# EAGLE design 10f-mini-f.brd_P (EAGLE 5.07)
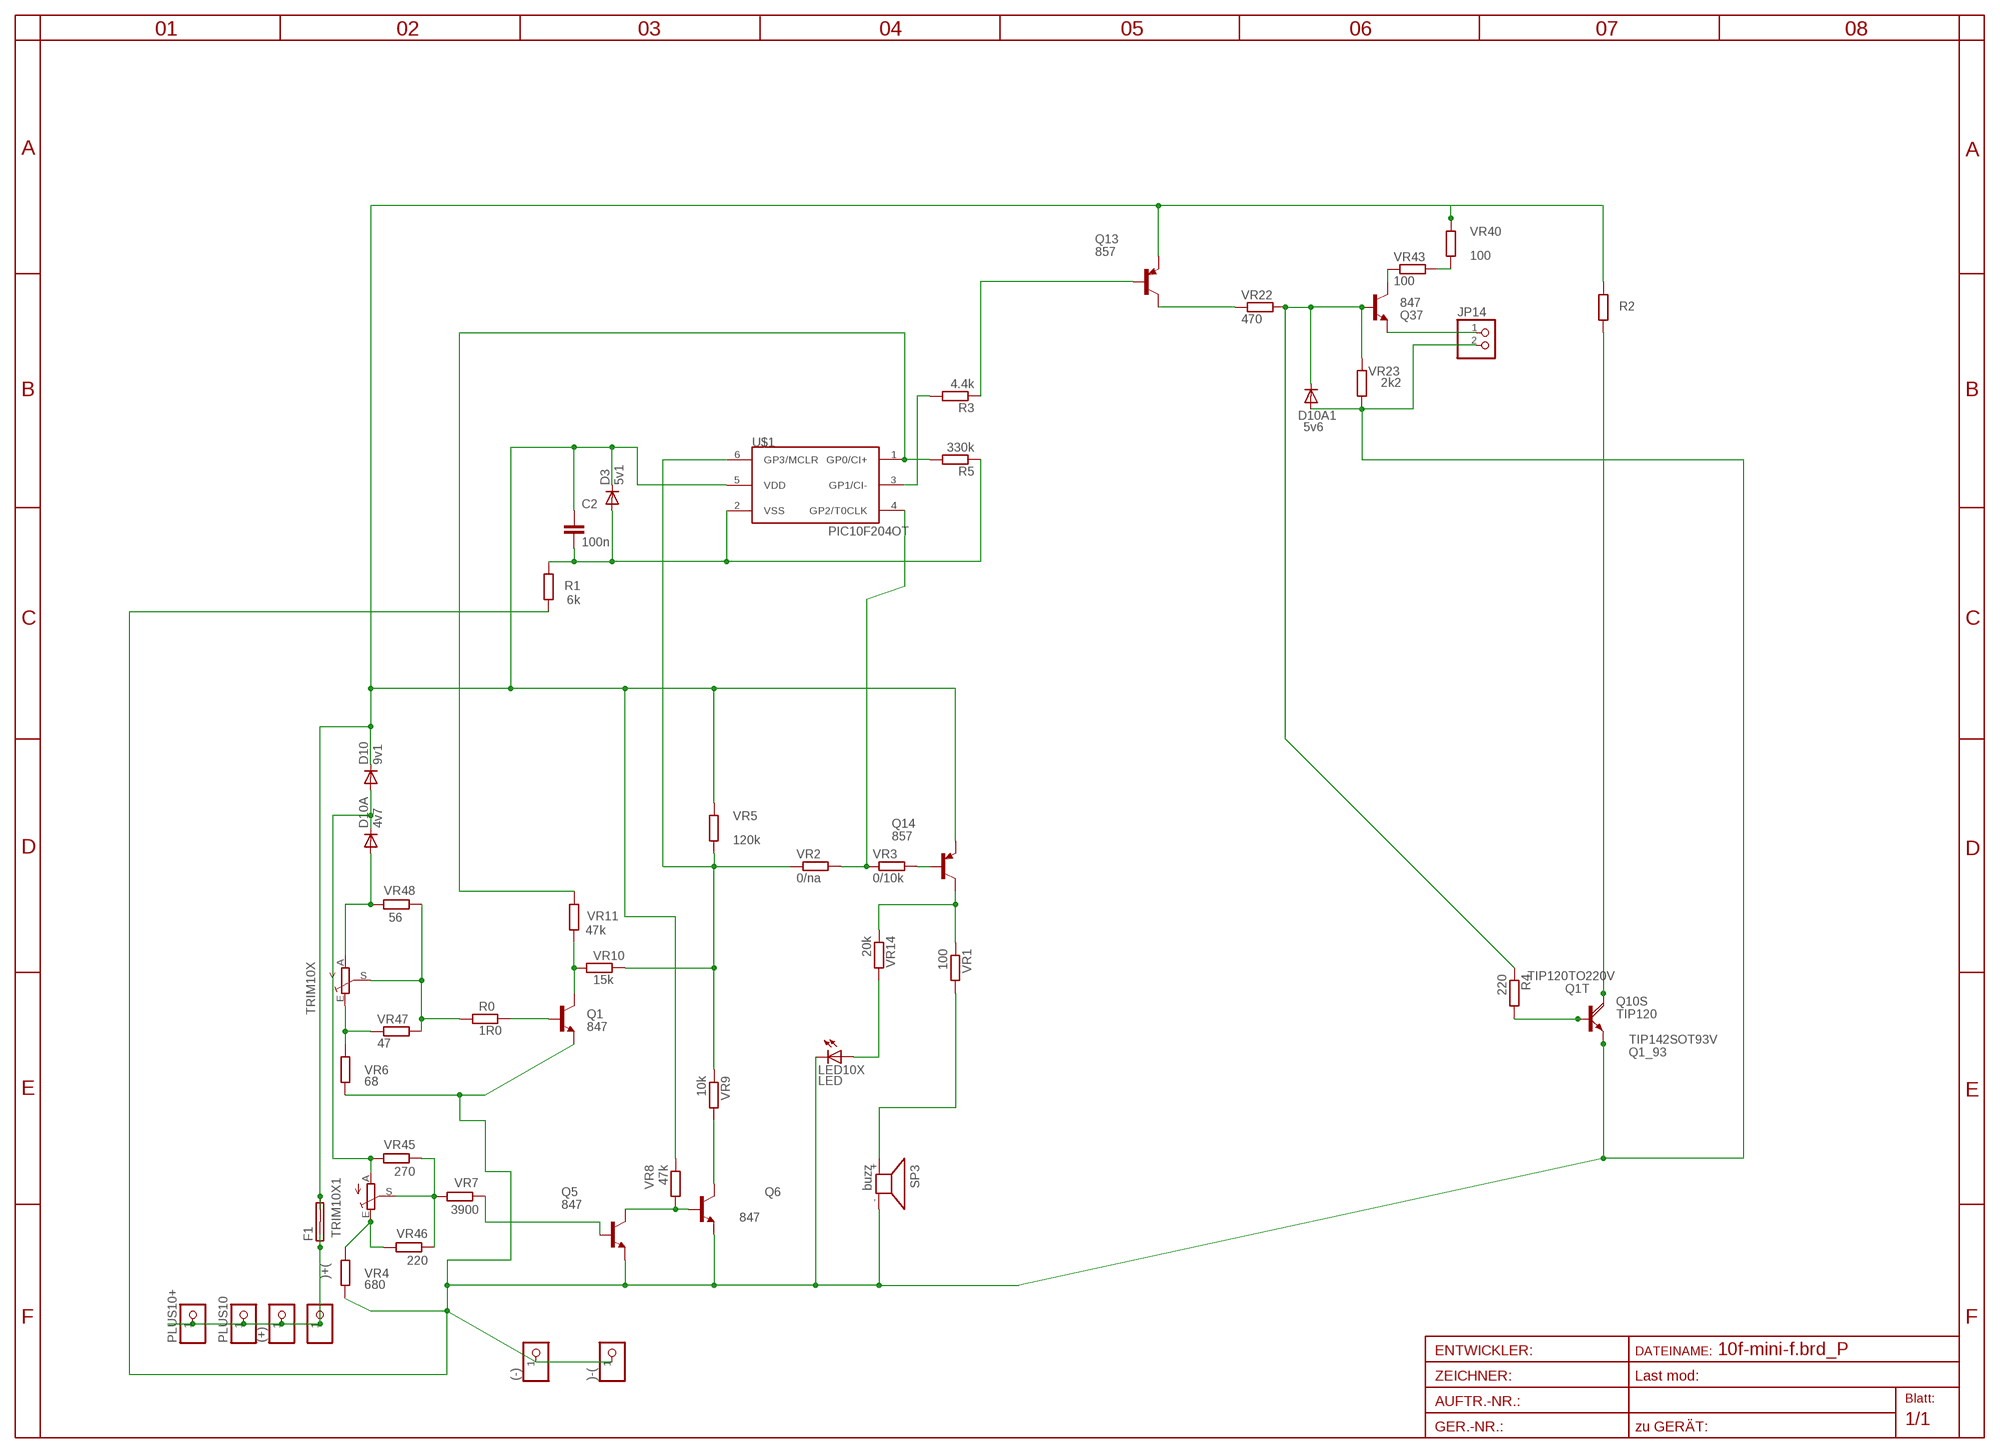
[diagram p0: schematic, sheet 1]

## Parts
(+)  PINHD-1X14.5MM  [1X4MM5]
(-)  PINHD-1X14.5MM  [1X4MM5]
)+(  PINHD-1X11X0.4  [1X01]
)-(  PINHD-1X11X0.4  [1X01]
C2  100n  C-EUC0805  [C0805]
D3  5v1  DIODE-MINIMELF  [MINIMELF]
D10  9v1  DIODE-MINIMELF  [MINIMELF]
D10A  4v7  DIODE-MINIMELF  [MINIMELF]
D10A1  5v6  DIODE-MINIMELF  [MINIMELF]
F1  SHK20L7MM5  [7MM5]
JP14  PINHD-1X2STR  [1X02]
LED10X  LED  LEDCHIPLED_1206  [CHIPLED_1206]
PLUS10  PINHD-1X14.5MM  [1X4MM5]
PLUS10+  PINHD-1X11X0.4  [1X01]
Q1  847  BC847CSMD  [SOT23]
Q1_93  TIP142SOT93V  [SOT93V]
Q1T  TIP120TO220V  [TO220AV]
Q5  847  BC847CSMD  [SOT23]
Q6  847  BC847CSMD  [SOT23]
Q10S  TIP120  TIP120DPAK  [D-PAK_TO252AA]
Q13  857  BC857CSMD  [SOT23-BEC]
Q14  857  BC857CSMD  [SOT23-BEC]
Q37  847  BC847CSMD  [SOT23]
R0  1R0  R-EU_R1206  [R1206]
R1  6k  R-EU_R0805  [R0805]
R2  R-EU_CERAM40  [CERAM40]
R3  4.4k  R-EU_R0805  [R0805]
R4  220  R-EU_R0805  [R0805]
R5  330k  R-EU_R0805  [R0805]
SP3  buzz  KSS12017MM  [KSS1202]
TRIM10X  TRIM_EU-S64W  [S64W]
TRIM10X1  TRIM_EU-S64W  [S64W]
U$1  PIC10F204OT  [SOT23-6]
VR1  100  R-EU_R0805  [R0805]
VR2  0/na  R-EU_R0805  [R0805]
VR3  0/10k  R-EU_R1206  [R1206]
VR4  680  R-EU_R0805  [R0805]
VR5  120k  R-EU_R0805  [R0805]
VR6  68  R-EU_R1206  [R1206]
VR7  3900  R-EU_M1206  [M1206]
VR8  47k  R-EU_R1206  [R1206]
VR9  10k  R-EU_R0805  [R0805]
VR10  15k  R-EU_R1206  [R1206]
VR11  47k  R-EU_R0805  [R0805]
VR14  20k  R-EU_R0805  [R0805]
VR22  470  R-EU_R0805  [R0805]
VR23  2k2  R-EU_R0805  [R0805]
VR40  100  R-EU_R1206  [R1206]
VR43  100  R-EU_R1206  [R1206]
VR45  270  R-EU_R0805  [R0805]
VR46  220  R-EU_R1206  [R1206]
VR47  47  R-EU_R0805  [R0805]
VR48  56  R-EU_R0805  [R0805]

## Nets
B: R0.1 TRIM10X.S VR47.2 VR48.1
BUZZ+: SP3.+ VR1.2
FPLUS: C2.1 D3.C D10.C F1.2A F1.2B Q13.E Q14.E R2.2 U$1.5(VDD) VR5.1 VR8.1 VR40.1
GP3: U$1.4(GP2/T0CLK) VR2.2 VR3.1
INPLUS: (+).1 )+(.1 F1.1A F1.1B PLUS10+.1 PLUS10.1
LEDA: LED10X.A VR14.2
N$1: R3.2 U$1.3(GP1/CI-)
N$2: Q1.3(C) VR10.1 VR11.1
N$3: Q5.3(C) Q6.1(B) VR8.2
N$5: Q6.3(C) VR9.2
N$6: U$1.6(GP3/MCLR) VR2.1 VR5.2 VR9.1 VR10.2
N$7: Q1.1(B) R0.2
N$8: Q14.C VR1.1 VR14.1
N$10: Q14.B VR3.2
N$14: D10A.A TRIM10X.A VR48.2
N$17: D10.A D10A.C TRIM10X1.A VR45.2
N$22: TRIM10X1.S VR7.2 VR45.1 VR46.1
N$23: Q13.B R3.1
N$24: TRIM10X1.E VR4.1 VR46.2
N$25: Q1_93.B Q1T.B Q10S.1(B) R4.2
N$128: TRIM10X.E VR6.1 VR47.1
N$136: JP14.1 Q37.2(E)
N$138: R5.2 U$1.1(GP0/CI+) VR11.2
N$159: Q13.C VR22.1
N$163: VR40.2 VR43.2
N$164: Q37.3(C) VR43.1
N$168: Q5.1(B) VR7.1
N$179: D10A1.C Q37.1(B) R4.1 VR22.2 VR23.1
Q10C: Q1_93.C Q1T.C Q10S.4(C) R2.1
VSS: (-).1 )-(.1 D10A1.A JP14.2 LED10X.C Q1.2(E) Q1_93.E Q1T.E Q5.2(E) Q6.2(E) Q10S.3(E) R1.1 SP3.- VR4.2 VR6.2 VR23.2
VSS1: C2.2 D3.A R1.2 R5.1 U$1.2(VSS)

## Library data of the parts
(+) (-) )+( )-( PLUS10 PLUS10+ = pinhead:PINHD-1X1: PIN HEADER
C2 = rcl:C-EU: CAPACITOR, European symbol
D3 D10 D10A D10A1 = diode:DIODE-: DIODE
F1 = fuse:SHK20L: FUSE HOLDER 5 x 20 mm, SH contact, SHH1 Schukat, E1073 Buerklin
JP14 = pinhead:PINHD-1X2: PIN HEADER
LED10X = led:LED: LED
Q1 Q5 Q6 Q37 = transistor-npn:BC847*: NPN Transistor
Q1_93 = transistor-power:TIP142: NPN DARLINGTON TRANSISTOR
Q1T Q10S = transistor-power:TIP120: NPN DARLINGTON TRANSISTOR
Q13 Q14 = transistor-pnp:BC857*: PNP Transistror
R0 R1 R3-R5 VR1-VR11 VR14 VR22 VR23 VR40 VR43 VR45-VR48 = rcl-2:R-EU_: RESISTOR, European symbol
R2 = rcl:R-EU_: RESISTOR, European symbol
SP3 = buzzer:KSS1201: SPEAKER
TRIM10X TRIM10X1 = pot:TRIM_EU-: POTENTIOMETER
U$1 = microchip-3:PIC10F2*: uPC nW 0,25/0,5k Program Flash memory Comparator

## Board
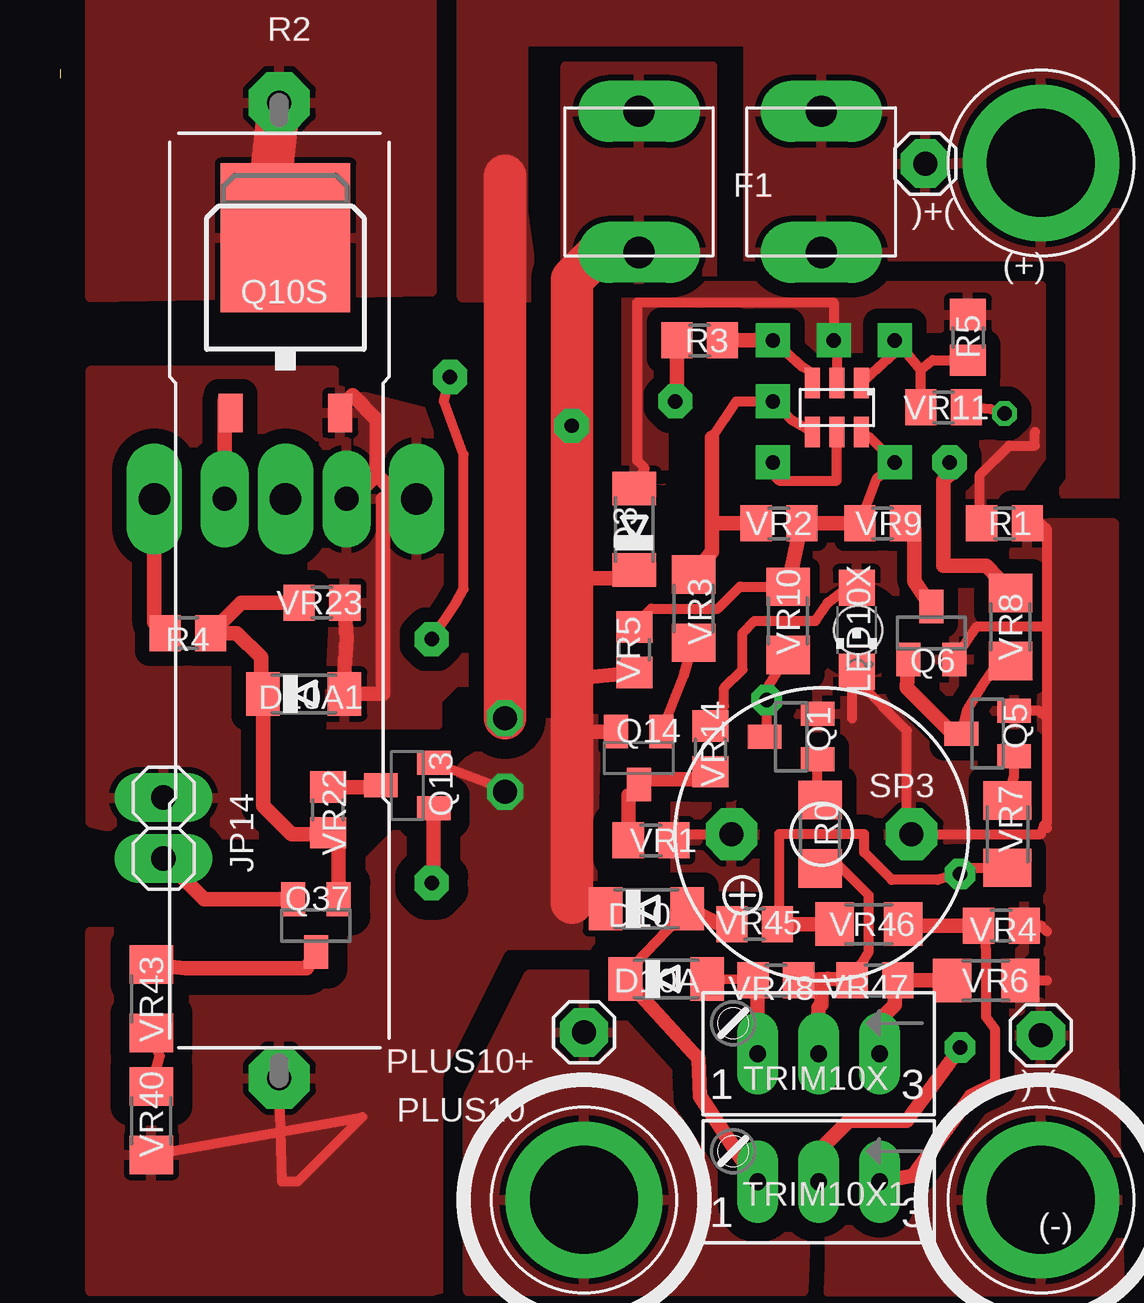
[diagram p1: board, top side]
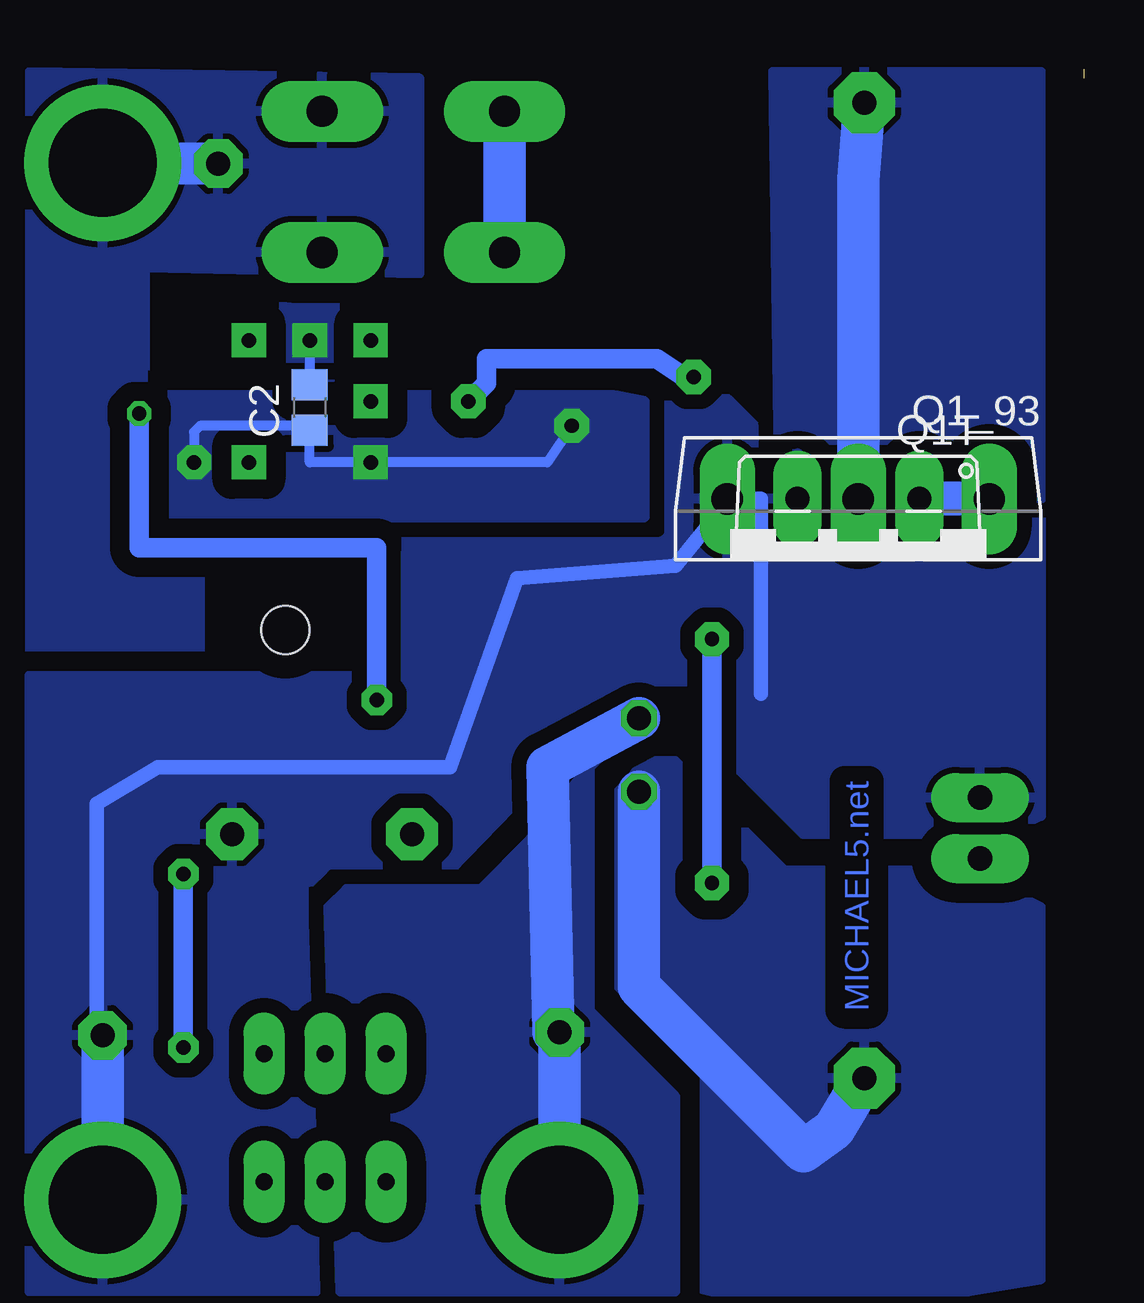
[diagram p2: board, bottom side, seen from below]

Size 0 x 0.37 mm. Coordinates in mm from the lower left corner, seen from the top.
Outline: 0,0.37 0,0
Copper layers (1*16): Top 0.035mm / dielectric 1.5mm / Bottom 0.035mm
Design rules "default *": minimum track width 8mil, minimum drill 4mil, track to track 8mil, track to pad 8mil, pad to pad 8mil, via to via 8mil, smd to smd 8mil, copper to edge 40mil, drill to drill 8mil, minimum pad ring 20mil, minimum via ring 8mil, stop-mask expansion 4mil, vias tented up to drill 0mil, thermal gap 10mil
Holes 2 mm at 33.27,-22.99

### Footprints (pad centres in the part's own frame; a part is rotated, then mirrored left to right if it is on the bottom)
1X4MM5 = drill 4.5 pad 6.35 round: 1 0,0
1X01 = drill 1 pad 1.676 octagon: 1 0,0
C0805 = smd 1.3 x 1.5: 1 -0.95,0; 2 0.95,0
MINIMELF = smd 1.4 x 1.8: A 1.7,0; C -1.7,0
7MM5 = drill 1.3 pad 2.54 long: 1A -3.8,2.94; 1B -3.8,-2.94; 2A 3.8,2.94; 2B 3.8,-2.94
1X02 = drill 1.016 pad 1.676 long: 1 -1.27,0; 2 1.27,0
CHIPLED_1206 = smd 1.5 x 1.5: A 0,-1.75; C 0,1.75
SOT23 = smd 1 x 1.4: 1 -0.95,-1.1; 2 0.95,-1.1; 3 0,1.1
SOT93V = drill 1.3 pad 1.676 long: B -5.461,-2.54; C 0,-2.54; E 5.461,-2.54
TO220AV = drill 1 pad 1.27 long: B -2.54,-2.54; C 0,-2.54; E 2.54,-2.54
D-PAK_TO252AA = smd 1 x 1.6: 1 -2.28,-4.8; 3 2.28,-4.8 | smd 5.4 x 6.2: 4 0,2.5
SOT23-BEC = smd 1 x 1.4: B -0.95,-1.1; C 0,1.1; E 0.95,-1.1
R1206 = smd 1.6 x 1.803: 1 -1.422,0; 2 1.422,0
R0805 = smd 1.3 x 1.5: 1 -0.95,0; 2 0.95,0
CERAM40 = drill 1 pad 2.54 octagon: 1 -20.32,0; 2 20.32,0
KSS1202 = drill 1 pad 2.159 octagon: + 3.75,0; - -3.75,0
S64W = drill 0.7 long: A 2.54,1.27; E -2.54,1.27; S 0,1.27
SOT23-6 = smd 0.635 x 1.27: 1 -1.016,-1.016; 2 0,-1.016; 3 1.016,-1.016; 4 1.016,1.016; 5 0,1.016; 6 -1.016,1.016
M1206 = smd 1.6 x 2: 1 -1.4,0; 2 1.4,0

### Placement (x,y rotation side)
(+)  40.89,-3.53 0 top  (outside the outline)
(-)  40.89,-46.74 0 top  (outside the outline)
)+(  36.07,-3.56 0 top  (outside the outline)
)-(  40.89,-39.88 0 top  (outside the outline)
C2  32.26,-13.72 90 bottom  (outside the outline)
D3  23.94,-18.8 90 top  (outside the outline)
D10  24.45,-34.61 0 top  (outside the outline)
D10A  25.27,-37.53 0 top  (outside the outline)
D10A1  10.16,-25.65 0 top  (outside the outline)
F1  27.94,-4.32 180 top  (outside the outline)
JP14  4.32,-31.24 90 top  (outside the outline)
LED10X  33.21,-22.99 180 top  (outside the outline)
PLUS10  21.84,-46.74 0 top  (outside the outline)
PLUS10+  21.84,-39.75 0 top  (outside the outline)
Q1  30.48,-27.43 90 top  (outside the outline)
Q1_93  9.4,-20.07 180 bottom  (outside the outline)
Q1T  9.4,-20.07 180 bottom  (outside the outline)
Q5  38.67,-27.3 90 top  (outside the outline)
Q6  36.32,-23.11 0 top  (outside the outline)
Q10S  9.4,-9.14 0 top  (outside the outline)
Q13  14.48,-29.46 90 top  (outside the outline)
Q14  24.13,-28.32 180 top  (outside the outline)
Q37  10.67,-35.31 180 top  (outside the outline)
R0  31.69,-31.5 90 top  (outside the outline)
R1  39.37,-18.54 180 top  (outside the outline)
R2  9.14,-21.34 270 top  (outside the outline)
R3  26.67,-10.92 0 top  (outside the outline)
R4  5.33,-23.11 180 top  (outside the outline)
R5  37.85,-10.79 270 top  (outside the outline)
SP3  31.75,-31.5 180 top  (outside the outline)
TRIM10X  31.62,-39.37 180 top  (outside the outline)
TRIM10X1  31.62,-44.7 180 top  (outside the outline)
U$1  32.38,-13.72 180 top  (outside the outline)
VR1  24.64,-31.75 0 top  (outside the outline)
VR2  29.97,-18.54 180 top  (outside the outline)
VR3  26.42,-22.1 270 top  (outside the outline)
VR4  39.24,-35.31 0 top  (outside the outline)
VR5  23.94,-23.81 90 top  (outside the outline)
VR6  38.61,-37.59 0 top  (outside the outline)
VR7  39.5,-31.5 270 top  (outside the outline)
VR8  39.62,-22.86 270 top  (outside the outline)
VR9  34.29,-18.54 0 top  (outside the outline)
VR10  30.35,-22.61 90 top  (outside the outline)
VR11  36.83,-13.72 180 top  (outside the outline)
VR14  27.11,-27.94 90 top  (outside the outline)
VR22  11.18,-30.48 270 top  (outside the outline)
VR23  10.92,-21.84 0 top  (outside the outline)
VR40  3.81,-43.43 90 top  (outside the outline)
VR43  3.81,-38.35 270 top  (outside the outline)
VR45  28.96,-35.24 180 top  (outside the outline)
VR46  33.72,-35.24 0 top  (outside the outline)
VR47  33.97,-37.59 180 top  (outside the outline)
VR48  29.84,-37.59 180 top  (outside the outline)

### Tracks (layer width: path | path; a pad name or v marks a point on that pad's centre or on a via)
B
  Top 0.406: VR47.2 33.27,-37.21 33.4,-36.89 33.72,-36.38 33.72,-34.04 32.47,-32.79 R0.1 | 31.62,-38.73 31.75,-38.61
  Top 0.61: 32,-37.53 VR48.1 | 32,-37.53 VR47.2 | TRIM10X.S 31.62,-38.73 | 31.75,-38.61 31.75,-37.78 32,-37.53
BUZZ+
  Top 0.406: SP3.+ 25.84,-31.5 VR1.2
  pour Top (isolate 0.61): 26.42,-29.72 29.97,-29.72 30.48,-30.23 30.48,-33.78 30.23,-34.04 26.42,-34.04 25.65,-33.27 25.65,-30.23
FPLUS  (via drill 0.6 pad 1.42, 1 pad 1.42)
  Top 0.406: 39.12,-20.83 VR8.1 | U$1.5 32.38,-16.76 29.97,-16.76 29.72,-16.51 v29.72,-16 | Q13.E 18.29,-29.53 18.22,-29.53 v18.54,-29.72 | VR40.1 12.6,-43.28 9.91,-45.97 9.25,-45.97 R2.2 | 21.34,-21.08 21.87,-21.84 | VR5.1 23.81,-24.89 | 24.24,-20.83 D3.C
  Top 0.61: 39.12,-20.83 38.61,-20.32 36.83,-20.32 36.83,-16.76 37.08,-16.51 v37.08,-16 | 21.34,-20.83 24.24,-20.83 | VR5.1 21.34,-25.02 21.34,-25.15 | Q14.E 21.34,-27.22 21.34,-27.18
  Top 1.778: 21.34,-34.36 21.34,-27.18 21.34,-25.15 21.34,-21.08 21.34,-20.83 v21.34,-14.48 21.34,-8.38 22.35,-7.37 24.03,-7.37 F1.2A
  Bottom 0.406: v37.08,-16 37.08,-14.73 36.83,-14.48 32.26,-14.48 C2.1 32.26,-16 v29.72,-16 22.35,-16 v21.34,-14.48
  Bottom 0.61: C2.1 32.38,-14.67
  Bottom 1.778: R2.2 10.41,-43.8 11.68,-44.7 18.54,-37.85 v18.54,-29.72 | F1.2A F1.2B
  pour Bottom (isolate 0.813, rank 2): 15.49,-50.55 4.83,-50.55 1.78,-50.04 1.78,-34.54 4.32,-33.27 4.57,-33.02 12.45,-33.02 17.02,-28.45 19.3,-28.45 20.32,-29.46 20.32,-38.86 16.51,-42.67 16.51,-50.29
  pour Top (isolate 0.813, rank 2): 15.49,-50.55 1.27,-50.55 1.27,-35.56 12.45,-35.56 12.45,-33.02 17.02,-28.45 19.56,-26.92 22.35,-26.67 22.1,-37.59 16.51,-42.67 16.51,-50.29
  pour Bottom (isolate 0.813): 18.29,-18.29 18.29,-13.46 19.56,-13.21 38.61,-13.21 38.61,-18.29
  pour Top (rank 4): 21.08,0.51 27.18,0.51 27.18,-8.38 21.08,-8.38
GP3  (via drill 0.6 pad 1.42)
  Top 0.406: U$1.4 30.48,-14.22 v29.72,-13.46 28.19,-13.46 27.18,-14.99
  Top 0.61: 27.18,-18.54 27.18,-14.99 | 27.18,-18.54 VR2.2 | 27.18,-18.54 27.18,-19.72 VR3.1
INPLUS  (via drill 1 pad 1.42)
  Top 1.778: v18.54,-26.67 18.54,-4.06
  Bottom 1.778: PLUS10.1 PLUS10+.1 22.1,-39.75 22.35,-28.7 v18.54,-26.67 | )+(.1 (+).1
  pour Bottom (isolate 0.813): 18.8,-26.42 23.11,-31.75 25.15,-33.78 30.73,-33.78 31.5,-34.54 30.99,-50.55 17.02,-50.55 17.02,-42.42 20.57,-38.86 20.57,-28.7 20.07,-28.19
  pour Bottom (isolate 0.813, rank 3): 43.94,0.25 43.94,-24.13 36.83,-24.13 36.83,-18.29 38.61,-18.29 39.12,-17.53 39.12,-7.87 27.69,-8.13 27.69,0
  pour Top (isolate 0.813): 31.5,-37.34 30.99,-50.55 17.02,-50.55 17.02,-42.42 19.56,-37.34
  pour Top (isolate 0.813, rank 3): 16.76,4.57 34.8,4.57 43.94,4.57 43.94,-18.29 29.46,-18.54 29.97,-18.03 38.61,-18.29 39.12,-17.53 38.61,-7.62 28.7,-7.62 28.7,1.52 19.3,1.52 19.3,-5.59 19.81,-9.14 16.76,-9.14
LEDA
  Top 0.406: VR14.2 27.37,-26.73 27.69,-26.16 27.69,-25.4 28.45,-24.64 28.45,-23.11 28.96,-22.61 31.5,-22.61 32,-21.84 32.7,-21.3 LED10X.A
  pour Top (isolate 0.406): 35.56,-22.61 35.56,-20.07 35.05,-19.56 31.75,-19.56 31.24,-20.07 31.24,-22.35 31.5,-22.61 32.77,-22.61
N$1
  Top 0.406: 29.72,-10.92 30.92,-12 31.31,-12.26 U$1.3
  Top 0.61: 29.72,-10.92 R3.2
N$2  (via drill 0.6 pad 1.02, 0.6 pad 1.27)
  Top 0.406: VR11.1 38.8,-13.78 v39.37,-13.97 | 30.86,-24.51 VR10.1 29.46,-25.42 v29.46,-25.91 29.46,-27.35 Q1.3
  Bottom 0.813: v29.46,-25.91 29.46,-19.56 39.37,-19.56 v39.37,-13.97
N$3
  Top 0.406: VR8.2 39.54,-23.71 38.42,-25.34 37.85,-26.27 Q5.3
  Top 0.61: Q6.1 35.31,-25.4 37.08,-27.18 37.45,-27.18 Q5.3
N$5
  Top 0.406: 35.56,-18.73 VR9.2
  Top 0.61: Q6.3 35.62,-20.95 35.62,-18.8 35.56,-18.73
N$6
  Top 0.406: VR9.1 34.04,-16.7 34.8,-16 33.78,-14.99 U$1.6 | VR10.2 28.35,-21.18 27.43,-22.1 24.64,-22.1 24.13,-22.6 VR5.2 | 30.86,-18.73 VR2.1
  Top 0.61: VR2.1 VR9.1 | VR10.2 30.86,-18.73
N$7
  Top 0.406: Q1.1 31.58,-29.97 R0.2
N$8
  Top 0.406: 26.92,-29.21 27.31,-28.83 VR14.1 | 24.53,-29.21 Q14.C 23.69,-29.86
  Top 0.61: 24.53,-29.21 26.92,-29.21 | VR1.1 23.69,-29.86
N$9  (via drill 0.6 pad 1.42)
  other vias: 34.8,-16
N$10
  Top 0.406: Q14.B 26.02,-24.87 VR3.2
N$11  (via drill 0.6 pad 1.42)
  other vias: 34.8,-10.92
N$14
  Top 0.406: 29.08,-37.59 VR48.2 D10A.A
  Top 0.61: TRIM10X.A 29.08,-37.59
N$17
  Top 0.406: 27.37,-35.18 VR45.2 | D10A.C 23.57,-37.31 D10.A
  Top 0.61: D10.A 27.37,-35.18 | D10A.C 26.62,-40.84 26.67,-42.42 28.45,-45.08 TRIM10X1.A
N$22  (via drill 0.6 pad 1.27)
  Top 0.406: VR45.1 29.97,-35.24 29.97,-31.5 33.53,-31.5 33.53,-32.26 34.67,-33.4 36.58,-33.4 v37.53,-33.15 37.91,-32.9 VR7.2
  Top 0.61: 29.97,-35.24 VR46.1 | TRIM10X1.S 31.62,-44.7 32.89,-43.43 35.31,-43.43 v37.53,-40.39
  Bottom 0.813: v37.53,-40.39 v37.53,-33.15
N$23  (via drill 0.6 pad 1.42)
  Top 0.406: v15.49,-23.37 16.51,-21.84 16.83,-21.27 16.83,-15.68 16,-13.46 v16.26,-12.45
  Top 0.61: R3.1 25.72,-13.14 v25.65,-13.46 | Q13.B 15.58,-32.68 v15.49,-33.53
  Bottom 0.61: v16.26,-12.45 16.26,-12.7
  Bottom 0.813: 16.26,-12.7 17.78,-11.68 24.89,-11.68 24.89,-12.7 v25.65,-13.46 | v15.49,-33.53 v15.49,-23.37
N$24
  Top 0.406: 38.99,-41.91 38.99,-39.62 38.61,-39.12 38.61,-36.32 38.55,-35.75 VR4.1 38.26,-35.5 | 35.01,-35.31 VR46.2
  Top 0.61: TRIM10X1.E 35.56,-45.72 37.97,-42.42 38.99,-41.91 | VR4.1 35.01,-35.31
N$25
  Top 0.61: Q1_93.B 3.94,-22.67 R4.2 | Q1T.B 6.86,-13.44 Q10S.1
  Bottom 1.422: Q1_93.B Q1T.B
N$128
  Top 0.406: 34.8,-37.59 VR47.1 34.8,-37.59
  Top 0.61: TRIM10X.E 34.16,-39.24 34.8,-38.61 34.8,-37.59 | 34.8,-37.59 VR6.1
N$136
  Top 0.61: Q37.2 6.01,-34.21 JP14.1
N$138
  Top 0.406: 35.87,-12.14 VR11.2 | 35.87,-12.14 35.12,-11.24 34.8,-10.92 34.8,-11.43 U$1.1 | R5.2 36.37,-11.74 35.87,-12.14
N$159
  Top 0.61: VR22.1 12.68,-29.53 Q13.C
N$163
  Top 0.406: VR40.2 4.17,-40.74 VR43.2
N$164
  Top 0.61: VR43.1 5.23,-37.08 10.29,-37.08 Q37.3
N$168
  Top 0.406: Q5.1 39.77,-29.06 VR7.1
N$179
  Top 0.61: Q37.1 11.62,-31.87 VR22.2 11.11,-31.5 9.65,-31.5 8.46,-30.3 D10A1.C 8.38,-25.58 8.38,-24.13 7.37,-23.11 R4.1 7.55,-21.84 VR23.1
Q10C
  Top 1.422: 9.65,-6.6 9.65,-6.14 Q10S.4
  Top 1.778: R2.1 8.64,-5.59 9.65,-6.6
  Bottom 1.778: Q1_93.C 9.4,-4.21 R2.1
  pour Top (isolate 0.813): 1.27,4.57 15.49,4.57 15.49,-8.89 1.27,-9.14
  pour Bottom (isolate 0.813): 1.78,0.25 12.95,0.25 12.7,-17.53 1.78,-17.53
VDF  (via drill 0.6 pad 1.42)
  other vias: 29.72,-10.92
VSS
  Top 0.406: VR4.2 40.89,-35.31 41.15,-35.56 | VR6.2 41.15,-37.59 | 41.02,-31.11 41.15,-31.24 | 41.02,-31.11 40.89,-31.5 SP3.- 35.31,-31.3 35.31,-27.18 33.21,-25.08 LED10X.C 33.02,-24.99 33.02,-26.67 | Q5.2 40.83,-26.35 41.15,-26.67 | 41.15,-26.67 41.15,-30.99 41.02,-31.11 | R1.1 40.89,-18.54 41.15,-18.8 41.15,-22.86 | 41.15,-26.67 41.15,-22.86 | Q6.2 38.21,-22.86 41.15,-22.86
  Top 0.61: VR23.2 11.94,-23.37 11.86,-24.56 D10A1.A 13.46,-25.65 13.46,-17.53 14.99,-17.65 Q1_93.E 14.22,-17.53 13.21,-16.51 | Q1T.E 12.19,-17.53 13.21,-16.51 | 13.21,-16.51 13.21,-14.22 12.19,-13.21 11.96,-13.46 Q10S.3
  Bottom 0.61: )-(.1 41.15,-39.62 41.15,-30.23 38.61,-28.7 26.42,-28.7 23.62,-20.83 17.02,-20.32 14.86,-17.65 Q1_93.E 13.46,-17.53 13.46,-25.65
  Bottom 1.778: )-(.1 (-).1
  pour Top (isolate 0.61): 32.51,-24.13 32.51,-26.16 31.5,-27.18 31.5,-28.96 35.56,-33.02 41.15,-33.02 41.4,-32.77 41.4,-30.23 40.64,-29.46 38.1,-29.46 38.1,-26.67 36.58,-25.91
  pour Bottom (isolate 0.61, rank 2): 43.94,-50.55 43.94,-24.89 28.45,-24.89 28.45,-17.27 18.8,-17.02 16.51,-11.68 13.21,-14.99 1.78,-17.78 1.78,-30.73 3.3,-31.5 11.68,-31.5 15.75,-27.43 15.75,-25.91 16.51,-25.15 18.8,-25.15 26.42,-33.02 32.51,-33.53 32,-50.55
  pour Top (isolate 0.61, rank 2): 44.2,-50.55 43.94,-40.89 43.94,-18.54 37.08,-18.54 37.08,-23.62 29.46,-23.62 29.46,-17.27 27.43,-17.02 11.43,-12.95 11.43,-12.19 1.27,-12.19 1.27,-30.99 3.3,-31.5 9.4,-31.5 9.65,-22.1 11.43,-21.84 11.18,-26.92 15.75,-26.92 15.75,-25.91 16.51,-25.15 18.8,-25.15 26.42,-33.02 32.51,-33.53 32,-50.55
VSS1  (via drill 0.6 pad 1.42)
  Top 0.406: 40.64,-14.73 40.64,-15.3 39.56,-15.3 38.35,-16.51 38.35,-18.35 | U$1.2 32.38,-11.18 v32.26,-10.92 32.26,-9.34 24.07,-9.34 24.07,-15.94 24.38,-16.26 D3.A | R5.1 38.1,-9.72
  Top 0.61: R1.2 38.35,-18.35
  Bottom 0.406: v32.26,-10.92 C2.2
  pour Top (isolate 0.61): 23.62,-16.51 23.62,-8.89 24.13,-8.64 40.89,-8.64 40.89,-15.81 39.37,-18.03 37.59,-18.03 37.59,-12.19 38.35,-11.43 38.35,-10.92 37.85,-10.41 34.29,-10.41 33.27,-11.43 31.24,-11.43 31.24,-11.18 30.48,-10.41 25.65,-10.41 25.15,-10.92 25.15,-16.76
  pour Bottom (isolate 0.813, rank 2): 27.69,-9.14 38.35,-9.14 38.35,-12.45 38.1,-12.45 27.69,-12.45

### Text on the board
Bottom: MICHAEL5.net
tTest: 4v4
Document: 1m | 10u | 10u | 300u | 2mA | 500u | 1m | 2m | 300u | 300u | 30u | 5m | 14m | 12m | 500u | 5m | 5m | 5m | 5m | 5m | 5m | 40m | 40m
